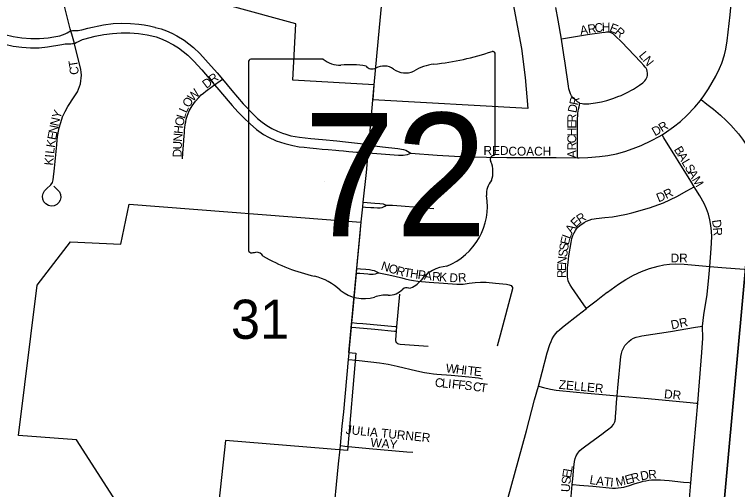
# Model space of a CAD drawing. Extents: x -209 to 4852, y 0 to 905.
# Drawn here: x 117.93 to 133.38, y 318.14 to 328.3 of the extents above; entities that cross this region are included whole.
import ezdxf

# ---------------------------------------------------------------- set-up
doc = ezdxf.new("R2010")
doc.units = 0
for name, color, linetype in [('GM_X_Airport_Location_Class_2', 7, 'Continuous'), ('GM_X_Airport_Location_Class_3', 7, 'Continuous'), ('GM_X_County_Subdivision_Text', 7, 'Continuous'), ('GM_X_Minor_River', 7, 'Continuous'), ('GM_X_Township_Road_Text', 7, 'Continuous'), ('GM_X_Township_ROW', 7, 'Continuous'), ('GM_X_Township_Subdivision', 7, 'Continuous'), ('GM_X_US_Location', 7, 'Continuous')]:
    doc.layers.add(name, color=color, linetype=linetype)

msp = doc.modelspace()

# ---------------------------------------------------------------- linework, layer by layer
at = {"layer": 'GM_X_Airport_Location_Class_2'}
for points in [[(119.129, 327.954), (119.118, 327.992), (119.002, 328.449), (118.923, 328.752), (118.885, 328.936), (118.857, 329.122), (118.848, 329.247), (118.845, 329.373), (118.85, 329.494), (118.866, 329.628), (118.908, 329.809), (118.989, 330.044), (119.15, 330.541)], [(132.602, 326.48), (132.662, 326.559), (132.764, 326.714), (132.919, 326.982), (133, 327.148), (133.047, 327.262), (133.105, 327.438), (133.133, 327.557), (133.161, 327.74), (133.225, 328.295), (133.277, 328.85), (133.331, 329.457)], [(129.617, 327.771), (129.549, 328.183), (129.498, 328.451)], [(116.751, 328.225), (117.189, 328.058), (117.539, 327.928), (117.717, 327.872), (117.9, 327.831), (118.085, 327.804), (118.272, 327.79), (118.459, 327.789), (118.645, 327.802), (118.769, 327.82), (118.892, 327.846), (118.952, 327.864), (119.01, 327.887), (119.05, 327.908), (119.087, 327.932), (119.11, 327.946), (119.129, 327.954)], [(116.684, 328.038), (116.842, 327.977), (117.305, 327.8), (117.538, 327.716), (117.716, 327.664), (117.897, 327.626), (118.08, 327.6), (118.265, 327.587), (118.45, 327.59), (118.634, 327.608), (118.94, 327.662), (119.007, 327.671), (119.073, 327.676), (119.133, 327.677), (119.167, 327.679), (119.189, 327.681), (119.206, 327.684)], [(119.129, 327.954), (119.167, 327.958), (119.206, 327.96), (119.245, 327.961), (119.285, 327.962), (119.321, 327.966), (119.365, 327.975), (119.492, 328.01), (119.826, 328.08), (120.033, 328.107), (120.217, 328.113), (120.403, 328.111), (120.587, 328.094), (120.697, 328.079), (120.811, 328.057), (120.926, 328.027)], [(120.926, 328.027), (120.934, 328.024), (121.06, 327.992), (121.177, 327.953), (121.29, 327.904), (121.399, 327.847), (121.556, 327.749), (121.656, 327.676), (121.75, 327.596), (121.885, 327.468), (122.012, 327.333), (122.257, 327.052), (122.37, 326.917)], [(119.164, 327.834), (119.129, 327.954)], [(119.206, 327.684), (119.246, 327.699), (119.296, 327.724), (119.352, 327.753), (119.378, 327.764), (119.411, 327.776), (119.651, 327.84), (119.835, 327.874), (120.02, 327.898), (120.207, 327.909), (120.394, 327.907), (120.58, 327.892), (120.765, 327.864), (120.862, 327.847), (120.863, 327.847)], [(130.013, 326.408), (130.061, 326.397), (130.089, 326.393), (130.129, 326.39), (130.164, 326.39), (130.207, 326.393), (130.246, 326.397), (130.346, 326.41), (130.473, 326.433), (130.589, 326.46), (130.738, 326.51), (130.825, 326.544), (130.897, 326.571), (130.994, 326.615), (131.158, 326.702), (131.287, 326.788), (131.357, 326.842), (131.398, 326.883), (131.422, 326.914), (131.438, 326.941), (131.45, 326.97), (131.455, 326.999), (131.458, 327.047), (131.452, 327.09), (131.443, 327.122), (131.428, 327.15), (131.411, 327.176), (131.382, 327.211), (131.319, 327.279), (130.902, 327.716), (130.769, 327.846), (130.721, 327.885), (130.693, 327.901), (130.66, 327.916), (130.637, 327.92), (130.605, 327.923), (130.581, 327.922), (130.55, 327.918), (130.482, 327.91), (130.176, 327.864), (129.617, 327.771)], [(119.206, 327.684), (119.164, 327.834)], [(120.863, 327.847), (120.955, 327.821), (121.046, 327.788), (121.161, 327.739), (121.327, 327.652), (121.433, 327.586), (121.534, 327.512), (121.63, 327.432), (121.763, 327.3), (121.93, 327.115), (122.201, 326.796)], [(130.013, 326.408), (129.963, 326.436), (129.923, 326.466), (129.897, 326.487), (129.878, 326.506), (129.858, 326.531), (129.835, 326.564), (129.815, 326.601), (129.796, 326.648), (129.777, 326.708), (129.767, 326.769), (129.696, 327.262), (129.671, 327.437), (129.617, 327.771)], [(118.765, 324.628), (118.818, 324.582), (118.863, 324.537), (118.886, 324.508), (118.911, 324.451), (118.918, 324.39), (118.905, 324.33), (118.874, 324.277), (118.828, 324.235), (118.773, 324.207), (118.711, 324.203), (118.651, 324.218), (118.598, 324.248), (118.556, 324.294), (118.532, 324.351), (118.526, 324.412), (118.539, 324.472), (118.567, 324.528), (118.607, 324.575), (118.7, 324.658), (118.737, 324.707), (118.755, 324.766), (118.784, 325.012), (118.822, 325.445), (118.848, 325.692), (118.881, 325.875), (118.914, 325.994), (118.955, 326.111), (119.007, 326.224), (119.067, 326.332), (119.205, 326.539), (119.27, 326.645), (119.297, 326.701), (119.319, 326.759), (119.335, 326.818), (119.346, 326.879), (119.353, 326.941), (119.355, 327.003), (119.352, 327.065), (119.343, 327.126), (119.318, 327.248), (119.218, 327.638), (119.206, 327.684)], [(121.518, 325.214), (121.526, 325.335), (121.541, 325.516), (121.553, 325.705), (121.557, 325.766), (121.562, 325.826), (121.569, 325.883), (121.576, 325.94), (121.586, 326.004), (121.597, 326.062), (121.617, 326.126), (121.638, 326.182), (121.659, 326.239), (121.722, 326.345), (121.758, 326.401), (121.796, 326.448), (121.865, 326.529), (121.918, 326.58), (121.967, 326.618), (122.018, 326.659), (122.153, 326.76), (122.201, 326.796)], [(122.201, 326.796), (122.323, 326.884), (122.37, 326.917)], [(122.201, 326.796), (122.293, 326.688), (122.495, 326.451), (122.576, 326.358), (122.701, 326.221), (122.828, 326.089), (122.961, 325.963), (123.1, 325.844), (123.248, 325.736), (123.354, 325.675), (123.523, 325.601), (123.708, 325.54), (123.878, 325.496), (124.013, 325.473), (124.122, 325.46), (124.243, 325.447), (124.382, 325.433), (124.503, 325.424), (124.635, 325.41), (124.793, 325.399), (124.86, 325.392), (124.962, 325.383), (125.075, 325.371), (125.161, 325.363), (125.238, 325.358), (125.311, 325.354), (125.488, 325.343)], [(122.37, 326.917), (122.574, 326.672), (122.818, 326.389), (123.033, 326.164), (123.124, 326.079), (123.221, 326.001), (123.323, 325.928), (123.43, 325.866), (123.55, 325.808), (123.653, 325.766), (123.726, 325.739), (123.836, 325.709), (124.021, 325.678), (124.26, 325.652), (124.513, 325.627), (124.814, 325.598), (125.005, 325.577), (125.192, 325.559), (125.326, 325.544), (125.503, 325.514)], [(131.768, 325.729), (131.866, 325.79), (132.016, 325.899), (132.16, 326.016), (132.297, 326.141), (132.468, 326.319), (132.588, 326.461), (132.602, 326.48)], [(132.602, 326.48), (132.725, 326.384), (132.866, 326.274), (133.015, 326.15), (133.141, 326.034), (133.239, 325.935), (133.403, 325.749), (133.487, 325.633), (133.586, 325.486), (133.688, 325.325), (133.975, 324.861), (134.084, 324.71), (134.149, 324.632), (134.21, 324.572), (134.258, 324.533), (134.308, 324.497), (134.385, 324.451)], [(129.963, 325.236), (129.962, 325.431), (129.962, 326.015), (129.963, 326.079), (129.966, 326.139), (129.972, 326.19), (129.977, 326.234), (129.985, 326.277), (129.995, 326.328), (130.013, 326.408)], [(129.963, 325.236), (129.998, 325.235), (130.183, 325.241), (130.43, 325.262), (130.613, 325.288), (130.795, 325.323), (130.974, 325.371), (131.149, 325.432), (131.321, 325.501), (131.545, 325.605), (131.709, 325.693), (131.768, 325.729)], [(132.459, 324.618), (132.386, 324.738), (131.81, 325.661), (131.768, 325.729)], [(125.503, 325.514), (125.68, 325.487), (125.796, 325.471), (126.124, 325.434), (126.244, 325.412), (126.291, 325.396), (126.328, 325.381), (126.402, 325.335)], [(125.488, 325.343), (126.133, 325.29), (126.233, 325.293), (126.328, 325.307), (126.402, 325.335)], [(126.402, 325.335), (126.96, 325.295), (127.58, 325.26), (128.449, 325.24), (129.132, 325.239), (129.504, 325.24), (129.963, 325.236)], [(130.051, 323.819), (130.105, 323.851), (130.154, 323.879), (130.208, 323.901), (130.271, 323.921), (130.316, 323.93), (130.359, 323.936), (130.549, 323.957), (130.71, 323.976), (130.827, 323.996), (131.01, 324.03), (131.124, 324.057), (131.502, 324.169), (131.797, 324.276), (132.083, 324.405), (132.302, 324.529), (132.459, 324.618)], [(132.788, 322.914), (132.818, 323.299), (132.83, 323.546), (132.828, 323.669), (132.815, 323.79), (132.791, 323.911), (132.759, 324.03), (132.719, 324.145), (132.669, 324.257), (132.58, 324.42), (132.459, 324.618)], [(125.373, 324.187), (125.431, 324.182), (125.547, 324.174), (125.611, 324.171), (125.685, 324.169), (125.74, 324.169), (125.786, 324.175), (125.813, 324.187), (125.845, 324.202), (125.882, 324.222)], [(125.383, 324.284), (125.628, 324.268), (125.739, 324.258), (125.805, 324.248), (125.839, 324.24), (125.882, 324.222)], [(125.882, 324.222), (125.941, 324.224), (126.007, 324.224), (126.193, 324.212), (126.893, 324.153)], [(130.151, 322.016), (130.097, 322.091), (129.837, 322.459), (129.802, 322.517), (129.776, 322.568), (129.763, 322.606), (129.753, 322.65), (129.749, 322.691), (129.746, 322.744), (129.747, 322.805), (129.75, 322.88), (129.759, 322.993), (129.778, 323.139), (129.824, 323.427), (129.843, 323.51), (129.864, 323.576), (129.887, 323.628), (129.919, 323.684), (129.939, 323.713), (129.971, 323.75), (130.001, 323.781), (130.044, 323.815), (130.051, 323.819)], [(130.594, 322.359), (130.601, 322.365), (130.839, 322.533), (130.997, 322.633), (131.16, 322.723), (131.329, 322.802), (131.504, 322.868), (131.684, 322.921), (131.807, 322.946), (131.931, 322.962), (132.057, 322.967), (132.244, 322.958), (132.788, 322.914)], [(132.633, 321.638), (132.66, 321.879), (132.733, 322.309), (132.769, 322.679), (132.788, 322.914)], [(132.788, 322.914), (133.046, 322.893), (133.911, 322.825), (133.972, 322.821), (134.074, 322.814)], [(125.236, 322.77), (125.309, 322.765), (125.483, 322.753), (125.514, 322.75), (125.57, 322.75), (125.591, 322.75), (125.645, 322.757), (125.681, 322.765), (125.712, 322.776)], [(125.246, 322.868), (125.321, 322.862), (125.438, 322.854), (125.515, 322.845), (125.571, 322.835), (125.618, 322.822), (125.659, 322.803), (125.712, 322.776)], [(125.712, 322.776), (125.822, 322.756), (125.895, 322.743), (126.06, 322.705), (126.207, 322.665), (126.281, 322.645), (126.369, 322.625), (126.459, 322.608), (126.55, 322.596), (126.791, 322.578), (127.096, 322.555), (127.385, 322.535), (127.456, 322.533), (127.521, 322.536), (127.645, 322.554), (127.777, 322.567), (127.889, 322.578), (128.011, 322.573), (128.212, 322.557), (128.368, 322.543), (128.446, 322.535), (128.504, 322.521), (128.542, 322.503), (128.561, 322.482), (128.571, 322.46), (128.571, 322.436), (128.309, 321.44), (128.244, 321.204)], [(126.101, 321.625), (126.163, 322.316)], [(130.151, 322.016), (130.163, 322.026), (130.358, 322.178), (130.503, 322.291), (130.594, 322.359)], [(129.125, 320.35), (129.207, 320.651), (129.315, 321.066), (129.372, 321.245), (129.397, 321.31), (129.421, 321.361), (129.453, 321.418), (129.492, 321.469), (129.535, 321.517), (129.582, 321.563), (129.673, 321.645), (129.97, 321.873), (130.151, 322.016)], [(125.139, 321.71), (125.247, 321.701), (125.374, 321.69), (126.061, 321.628), (126.101, 321.625)], [(125.129, 321.611), (125.22, 321.603), (125.631, 321.567), (126.05, 321.53), (126.091, 321.527)], [(126.768, 321.201), (126.17, 321.244), (126.144, 321.248), (126.122, 321.258), (126.105, 321.269), (126.092, 321.281), (126.083, 321.297), (126.078, 321.319), (126.077, 321.342), (126.091, 321.527)], [(126.091, 321.527), (126.101, 321.625)], [(130.81, 320.142), (130.825, 320.313), (130.889, 320.988), (130.9, 321.049), (130.918, 321.108), (130.942, 321.165), (130.974, 321.218), (131.013, 321.266), (131.058, 321.309), (131.108, 321.346), (131.162, 321.377), (131.219, 321.401), (131.279, 321.417), (131.339, 321.429), (131.953, 321.524), (132.484, 321.614), (132.633, 321.638)], [(132.532, 319.986), (132.553, 320.268), (132.621, 321.071), (132.638, 321.381), (132.633, 321.638)], [(125.065, 320.922), (125.231, 320.904), (125.543, 320.87), (125.73, 320.85), (125.917, 320.82), (126.103, 320.782), (126.528, 320.678), (126.692, 320.642), (126.792, 320.627), (126.881, 320.616), (126.952, 320.61), (127.263, 320.584), (127.639, 320.554), (127.771, 320.539), (127.845, 320.527), (127.934, 320.509)], [(128.348, 317.202), (128.356, 317.298), (128.386, 317.548), (128.407, 317.676), (128.415, 317.716), (128.424, 317.764), (128.478, 317.972), (128.695, 318.747), (128.868, 319.393), (129.045, 320.056), (129.125, 320.35)], [(129.125, 320.35), (129.154, 320.342), (129.234, 320.32), (129.383, 320.288), (129.508, 320.268), (129.939, 320.226), (130.81, 320.142)], [(129.849, 318.248), (129.859, 318.37), (129.881, 318.621), (129.897, 318.737), (129.915, 318.804), (129.936, 318.862), (129.97, 318.921), (130.015, 318.972), (130.057, 319.013), (130.11, 319.053), (130.511, 319.349), (130.556, 319.382), (130.603, 319.416), (130.694, 319.491), (130.731, 319.532), (130.747, 319.558), (130.761, 319.588), (130.767, 319.611), (130.769, 319.63), (130.77, 319.637), (130.772, 319.646), (130.772, 319.659), (130.775, 319.693), (130.788, 319.871), (130.798, 320.007), (130.81, 320.142)], [(130.81, 320.142), (131.469, 320.086), (132.142, 320.023), (132.367, 320.001), (132.495, 319.99), (132.532, 319.986)], [(132.384, 318.285), (132.449, 319.03), (132.501, 319.586), (132.532, 319.986)], [(124.892, 319.08), (124.988, 319.071), (125.134, 319.056), (125.511, 319.021), (126.316, 318.947), (126.44, 318.936)], [(129.849, 318.248), (129.866, 318.246), (130.007, 318.236), (130.29, 318.21), (130.711, 318.17), (130.772, 318.17), (130.831, 318.174), (130.892, 318.181), (130.954, 318.193), (131.072, 318.227), (131.173, 318.26), (131.246, 318.284), (131.301, 318.3), (131.366, 318.318), (131.425, 318.328), (131.486, 318.337), (131.547, 318.345), (131.611, 318.349), (131.735, 318.349), (131.82, 318.341), (131.92, 318.333), (132.231, 318.301), (132.348, 318.288), (132.384, 318.285)], [(132.266, 316.844), (132.278, 316.992), (132.351, 317.854), (132.384, 318.285)], [(129.751, 317.077), (129.753, 317.108), (129.759, 317.197), (129.767, 317.311), (129.798, 317.686), (129.826, 317.988), (129.849, 318.248)]]:
    msp.add_lwpolyline(points, dxfattribs=at)
at = {"layer": 'GM_X_County_Subdivision_Text'}
for points in [[(125.616, 326.788), (125.616, 326.796), (125.731, 328.026), (125.801, 328.777), (125.823, 329.009), (125.879, 329.631), (125.935, 330.249), (125.986, 330.787), (125.989, 330.806), (126.043, 331.318), (126.045, 331.335), (126.111, 332.146), (126.166, 333.021), (126.185, 333.58)], [(125.589, 326.469), (125.59, 326.474), (125.616, 326.788)], [(125.34, 323.867), (125.373, 324.187), (125.383, 324.284), (125.45, 324.925), (125.488, 325.343), (125.503, 325.514), (125.524, 325.731), (125.589, 326.469)], [(125.077, 321.06), (125.087, 321.162), (125.129, 321.611), (125.139, 321.71), (125.151, 321.838), (125.235, 322.76), (125.236, 322.77), (125.246, 322.868), (125.317, 323.613), (125.339, 323.864), (125.34, 323.867)], [(124.885, 319.001), (124.885, 319.003), (124.892, 319.08), (124.932, 319.496), (124.963, 319.804), (125.065, 320.922), (125.077, 321.06)], [(124.53, 315.291), (124.552, 315.53), (124.597, 316.026), (124.64, 316.466), (124.712, 317.202), (124.734, 317.434), (124.854, 318.689), (124.885, 319.001)]]:
    msp.add_lwpolyline(points, dxfattribs=at)
at = {"layer": 'GM_X_Minor_River'}
for points in [[(114.544, 335.599), (134.543, 333.757), (132.725, 313.81), (112.672, 315.623)], [(134.543, 333.757), (154.664, 331.913), (152.852, 311.89), (132.725, 313.81)]]:
    msp.add_lwpolyline(points, close=True, dxfattribs=at)
at = {"layer": 'GM_X_Township_Subdivision'}
for p, q in [((128.202, 325.352), (128.202, 327.446)), ((122.928, 327.278), (122.928, 323.276)), ((124.525, 327.347), (122.98, 327.347)), ((128.201, 325.353), (128.202, 325.352))]:
    msp.add_line(p, q, dxfattribs=at)
for centre, radius, start, end in [((126.323, 332.803), 5.592, 275.8445, 288.9065), ((128.143, 327.455), 0.0587, 351.8621, 97.738), ((122.989, 327.286), 0.0611, 98.1301, 188.1301), ((124.892, 327.811), 0.593, 231.6195, 271.1119), ((127.037, 326.124), 1.125, 97.3462, 120.7689), ((125.089, 325.1), 2.127, 80.4867, 94.9883), ((125.572, 327.307), 0.171, 219.7921, 297.1024), ((125.823, 326.845), 0.355, 54.4667, 119.1411), ((126.282, 327.479), 0.428, 233.8562, 294.8282), ((128.188, 325.199), 0.0909, 107.944, 210.337), ((128.139, 325.344), 0.0628, 289.6038, 7.7341), ((127.61, 324.934), 0.545, 340.033, 23.6496), ((128.412, 324.476), 0.397, 136.8065, 186.9296), ((126.637, 324.21), 1.399, 292.3089, 8.9858), ((122.989, 323.267), 0.0616, 171.9584, 258.3066), ((123.095, 323.045), 0.17, 29.7484, 93.2717), ((122.999, 323.676), 0.47, 267.339, 280.6039), ((125.236, 326.641), 4.038, 240.4129, 257.1985), ((127.226, 322.152), 0.766, 94.4031, 142.5768), ((124.032, 321.477), 1.264, 47.1842, 75.836), ((126.256, 322.888), 0.452, 282.8732, 323.2771), ((126.307, 322.337), 0.12, 65.7517, 132.6484), ((125.399, 323.025), 0.802, 230.7004, 286.2918), ((125.862, 321.641), 0.659, 85.6951, 111.2099), ((125.921, 322.725), 0.427, 268.777, 315.5493)]:
    msp.add_arc(centre, radius, start, end, dxfattribs=at)
at = {"layer": 'GM_X_US_Location'}
msp.add_lwpolyline([(128.544, 328.759), (128.762, 327.574), (128.845, 326.953), (128.897, 326.293), (125.589, 326.474), (125.616, 326.796), (123.873, 326.895), (123.939, 328.101), (122.558, 328.476)], dxfattribs=at)
msp.add_lwpolyline([(120.935, 316.587), (119.254, 319.204), (118.009, 319.294), (118.413, 322.511), (119.122, 323.436), (120.201, 323.392), (120.381, 324.242), (125.327, 323.858), (125.063, 321.073), (125.225, 321.059), (125.044, 318.972), (122.435, 319.186), (121.962, 314.769), (120.871, 314.844)], close=True, dxfattribs=at)

# ---------------------------------------------------------------- texts
at = {"layer": 'GM_X_Airport_Location_Class_3'}
for s, height, rotation, p in [('A', 0.189, 8.9988, (130.029, 327.865)), ('R', 0.189, 9.0285, (130.194, 327.891)), ('C', 0.189, 8.9991, (130.342, 327.914)), ('H', 0.189, 1.5299, (130.484, 327.937)), ('E', 0.189, 339.2233, (130.631, 327.945)), ('R', 0.189, 319.5383, (130.741, 327.906)), ('L', 0.189, 309.8336, (131.262, 327.419)), ('N', 0.189, 308.6359, (131.347, 327.318)), ('T', 0.189, 98.7777, (119.288, 327.184)), ('C', 0.189, 93.4991, (119.299, 327.016)), ('D', 0.189, 37.6392, (122.03, 326.707)), ('R', 0.189, 36.1559, (122.161, 326.808)), ('W', 0.189, 46.4267, (121.74, 326.427)), ('O', 0.189, 56.3887, (121.654, 326.295)), ('R', 0.189, 78.1614, (129.968, 326.349)), ('L', 0.189, 65.0722, (121.601, 326.181)), ('D', 0.189, 78.5357, (129.935, 326.186)), ('Y', 0.189, 69.6639, (118.899, 326.057)), ('L', 0.189, 72.9475, (121.564, 326.06)), ('R', 0.189, 89.9028, (129.934, 325.996)), ('N', 0.189, 77.8671, (118.866, 325.901)), ('O', 0.189, 78.5786, (121.533, 325.901)), ('E', 0.189, 89.9073, (129.934, 325.863)), ('R', 0.189, 31.1814, (131.765, 325.779)), ('N', 0.189, 79.5388, (118.836, 325.738)), ('H', 0.189, 84.6591, (121.518, 325.741)), ('H', 0.189, 89.8907, (129.934, 325.696)), ('D', 0.189, 30.0377, (131.618, 325.694)), ('E', 0.189, 79.5583, (118.812, 325.607)), ('N', 0.189, 85.4487, (121.505, 325.575)), ('C', 0.189, 89.8991, (129.933, 325.546)), ('K', 0.189, 80.6922, (118.785, 325.444)), ('U', 0.189, 88.251, (121.5, 325.411)), ('R', 0.189, 89.9028, (129.933, 325.396)), ('L', 0.189, 84.0882, (118.772, 325.314)), ('D', 0.189, 89.8907, (121.499, 325.246)), ('RED', 0.1894, 0, (127.952, 325.298)), ('COACH', 0.1894, 0, (128.485, 325.282)), ('A', 0.189, 89.9126, (129.933, 325.229)), ('B', 0.189, 300.8263, (132.016, 325.414)), ('K', 0.189, 84.9441, (118.75, 325.066)), ('I', 0.189, 84.9667, (118.764, 325.232)), ('A', 0.189, 300.7913, (132.093, 325.286)), ('L', 0.189, 300.8426, (132.178, 325.142)), ('S', 0.189, 300.8091, (132.246, 325.028)), ('A', 0.189, 300.8213, (132.315, 324.913)), ('M', 0.189, 301.3681, (132.401, 324.768)), ('D', 0.189, 22.2398, (131.694, 324.281)), ('R', 0.189, 26.1725, (131.861, 324.35)), ('R', 0.189, 32.3967, (130.012, 323.823)), ('E', 0.189, 44.8455, (129.926, 323.735)), ('D', 0.189, 277.5181, (132.837, 323.902)), ('A', 0.189, 57.6679, (129.844, 323.603)), ('R', 0.189, 274.3261, (132.858, 323.739)), ('E', 0.189, 77.243, (129.774, 323.364)), ('L', 0.189, 69.3097, (129.802, 323.488)), ('S', 0.189, 80.7263, (129.753, 323.236)), ('S', 0.189, 81.1666, (129.733, 323.104)), ('N', 0.189, 84.483, (129.717, 322.941)), ('DR', 0.1894, 0, (131.952, 322.998)), ('N', 0.189, 342.277, (125.746, 322.847)), ('O', 0.189, 342.2914, (125.905, 322.796)), ('R', 0.189, 343.9784, (126.07, 322.743)), ('E', 0.189, 89.6175, (129.717, 322.812)), ('T', 0.189, 350.6131, (126.237, 322.697)), ('H', 0.189, 351.885, (126.373, 322.674)), ('P', 0.189, 351.9096, (126.538, 322.651)), ('A', 0.189, 353.0063, (126.674, 322.632)), ('R', 0.189, 355.1026, (126.847, 322.61)), ('K', 0.189, 355.365, (126.998, 322.598)), ('D', 0.189, 357.0316, (127.219, 322.58)), ('R', 0.189, 4.7926, (127.414, 322.572)), ('R', 0.189, 89.8543, (129.716, 322.663)), ('DR', 0.1894, 11.8927, (131.978, 321.564)), ('W', 0.189, 353.411, (127.139, 320.648)), ('H', 0.189, 353.4064, (127.355, 320.623)), ('I', 0.189, 353.423, (127.52, 320.604)), ('T', 0.189, 353.4003, (127.603, 320.595)), ('E', 0.189, 354.36, (127.739, 320.579)), ('C', 0.189, 354.2846, (126.906, 320.341)), ('L', 0.189, 354.2861, (127.056, 320.326)), ('I', 0.189, 354.2633, (127.188, 320.313)), ('F', 0.189, 354.3007, (127.271, 320.304)), ('F', 0.189, 354.2541, (127.404, 320.291)), ('S', 0.189, 353.8952, (127.536, 320.278)), ('C', 0.189, 351.3443, (127.716, 320.257)), ('ZELLER', 0.1894, 354.5067, (129.555, 320.296)), ('T', 0.189, 351.782, (127.866, 320.235)), ('DR', 0.1894, 353.9832, (131.805, 320.096)), ('JULIA TURNER', 0.18939, 354.2885, (125, 319.332)), ('WAY', 0.1894, 354.8086, (125.53, 319.057)), ('L', 0.189, 80.614, (129.84, 318.507)), ('E', 0.189, 81.4719, (129.82, 318.376)), ('L', 0.189, 350.8925, (130.21, 318.262)), ('M', 0.189, 13.0008, (130.802, 318.201)), ('E', 0.189, 15.2809, (131.005, 318.248)), ('R', 0.189, 15.2615, (131.134, 318.283)), ('D', 0.189, 10.9499, (131.323, 318.333)), ('R', 0.189, 5.2274, (131.482, 318.364)), ('S', 0.189, 84.583, (129.808, 318.246)), ('A', 0.189, 353.1979, (130.35, 318.239)), ('T', 0.189, 353.525, (130.517, 318.22)), ('I', 0.189, 354.7149, (130.654, 318.204)), ('U', 0.189, 85.8265, (129.796, 318.08))]:
    msp.add_text(s, height=height, rotation=rotation, dxfattribs=at).set_placement(p)
at = {"layer": 'GM_X_Township_Road_Text'}
msp.add_text('31', height=0.8371, rotation=0, dxfattribs=at).set_placement((122.552, 321.364))
at = {"layer": 'GM_X_Township_ROW'}
for s in ['s', 'r']:
    msp.add_text(s, height=0.00379, dxfattribs=at).set_placement((125.506, 325.011))
msp.add_text('72', height=0.00379, rotation=0, dxfattribs=at).set_placement((124.552, 324.735))
at = {"layer": 'GM_X_Township_Subdivision'}
msp.add_text('72', height=2.6367, dxfattribs=at).set_placement((124.108, 323.558))

doc.saveas('drawing.dxf')
